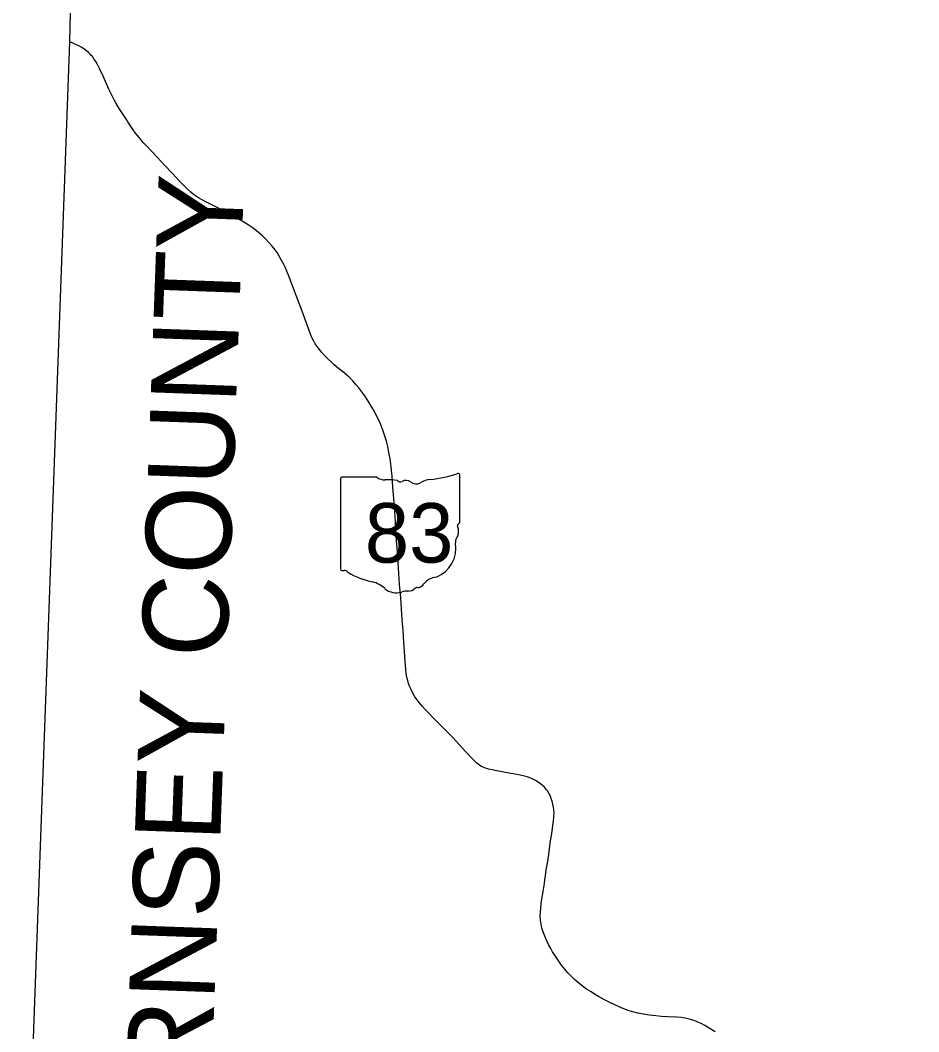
# Model space of a CAD drawing. Extents: x 2125567 to 2397567, y 653347 to 829347.
# Drawn here: x 2184839 to 2195345, y 708922 to 720753 of the extents above; entities that cross this region are included whole.
import ezdxf

# ---------------------------------------------------------------- set-up
doc = ezdxf.new("R2010")
doc.units = 0
for name, color, linetype in [('GM_X_County', 7, 'Continuous'), ('GM_X_County_Text', 7, 'Continuous'), ('GM_X_State_Route', 7, 'Continuous'), ('GM_X_State_Shield', 7, 'Continuous')]:
    doc.layers.add(name, color=color, linetype=linetype)

msp = doc.modelspace()

# ---------------------------------------------------------------- linework, layer by layer
at = {"layer": 'GM_X_County'}
msp.add_lwpolyline([(2195235, 695229), (2195244, 698121), (2195345, 704208), (2193259, 704276), (2191227, 704339), (2187691, 704452), (2186198, 704526), (2186181, 704528), (2186154, 704528), (2184839, 704570), (2185417, 720500), (2185450, 721840), (2185440, 722692), (2185445, 722809), (2185639, 727493), (2185641, 727535), (2185674, 729391), (2185791, 731433), (2186112, 740356), (2186166, 742913), (2186360, 747780)], dxfattribs=at)
at = {"layer": 'GM_X_State_Route'}
msp.add_lwpolyline([(2192963, 708921), (2192894, 708964), (2192843, 708994), (2192800, 709017), (2192761, 709035), (2192719, 709052), (2192676, 709066), (2192645, 709075), (2192613, 709081), (2192568, 709087), (2192512, 709092), (2192411, 709097), (2192338, 709101), (2192270, 709107), (2192191, 709116), (2192126, 709126), (2192059, 709140), (2192001, 709154), (2191947, 709170), (2191895, 709189), (2191840, 709212), (2191790, 709236), (2191734, 709263), (2191672, 709295), (2191600, 709334), (2191555, 709361), (2191513, 709387), (2191461, 709422), (2191445, 709433), (2191413, 709457), (2191369, 709491), (2191319, 709534), (2191279, 709573), (2191240, 709613), (2191206, 709653), (2191169, 709700), (2191135, 709748), (2191097, 709805), (2191064, 709858), (2191037, 709904), (2191016, 709944), (2190991, 709995), (2190972, 710040), (2190956, 710080), (2190943, 710120), (2190933, 710156), (2190928, 710181), (2190921, 710227), (2190919, 710273), (2190921, 710320), (2190925, 710366), (2190931, 710421), (2190943, 710496), (2190953, 710561), (2190967, 710655), (2190973, 710703), (2190980, 710746), (2190990, 710814), (2191003, 710894), (2191018, 710995), (2191028, 711066), (2191040, 711154), (2191053, 711235), (2191068, 711335), (2191075, 711390), (2191079, 711436), (2191080, 711481), (2191078, 711520), (2191075, 711546), (2191068, 711584), (2191058, 711619), (2191048, 711649), (2191033, 711685), (2191018, 711714), (2191003, 711739), (2190994, 711751), (2190986, 711763), (2190967, 711784), (2190945, 711804), (2190923, 711822), (2190893, 711843), (2190862, 711861), (2190831, 711877), (2190798, 711891), (2190767, 711902), (2190733, 711911), (2190669, 711926), (2190556, 711947), (2190411, 711972), (2190356, 711984), (2190314, 711994), (2190279, 712005), (2190261, 712013), (2190234, 712025), (2190212, 712038), (2190195, 712051), (2190177, 712065), (2190150, 712090), (2190106, 712134), (2190045, 712199), (2189896, 712363), (2189836, 712427), (2189762, 712501), (2189667, 712595), (2189619, 712644), (2189578, 712687), (2189538, 712731), (2189505, 712772), (2189478, 712806), (2189454, 712841), (2189431, 712881), (2189412, 712919), (2189396, 712956), (2189380, 712996), (2189370, 713030), (2189360, 713069), (2189353, 713111), (2189347, 713160), (2189340, 713258), (2189325, 713477), (2189315, 713614), (2189306, 713739), (2189287, 713996), (2189275, 714159), (2189250, 714531), (2189240, 714668), (2189232, 714773), (2189225, 714894), (2189211, 715113), (2189197, 715293), (2189187, 715426), (2189184, 715457), (2189176, 715531), (2189163, 715622), (2189150, 715696), (2189135, 715767), (2189120, 715830), (2189102, 715890), (2189084, 715946), (2189063, 716001), (2189042, 716052), (2189025, 716087), (2189001, 716137), (2188970, 716195), (2188943, 716240), (2188902, 716307), (2188867, 716358), (2188833, 716406), (2188797, 716453), (2188767, 716488), (2188726, 716534), (2188683, 716577), (2188659, 716600), (2188625, 716629), (2188561, 716680), (2188511, 716722), (2188481, 716748), (2188434, 716793), (2188399, 716828), (2188366, 716865), (2188336, 716900), (2188311, 716935), (2188289, 716968), (2188271, 716999), (2188254, 717035), (2188233, 717083), (2188202, 717166), (2188134, 717351), (2188085, 717483), (2188034, 717615), (2187983, 717750), (2187957, 717817), (2187936, 717865), (2187920, 717897), (2187891, 717952), (2187864, 718000), (2187841, 718036), (2187831, 718050), (2187818, 718068), (2187784, 718111), (2187750, 718151), (2187707, 718196), (2187672, 718230), (2187625, 718271), (2187582, 718306), (2187550, 718329), (2187504, 718360), (2187454, 718391), (2187356, 718449), (2187348, 718453), (2187313, 718473), (2187224, 718522), (2187166, 718552), (2187095, 718588), (2186987, 718642), (2186958, 718658), (2186924, 718677), (2186890, 718699), (2186866, 718716), (2186835, 718741), (2186798, 718774), (2186751, 718820), (2186695, 718879), (2186622, 718955), (2186528, 719055), (2186443, 719146), (2186311, 719288), (2186278, 719324), (2186233, 719376), (2186210, 719405), (2186188, 719433), (2186161, 719470), (2186128, 719519), (2186113, 719541), (2186097, 719565), (2186088, 719579), (2186041, 719650), (2185995, 719722), (2185965, 719773), (2185942, 719813), (2185897, 719900), (2185876, 719945), (2185807, 720097), (2185766, 720187), (2185743, 720234), (2185722, 720271), (2185701, 720303), (2185683, 720327), (2185669, 720342), (2185662, 720351), (2185636, 720376), (2185612, 720397), (2185583, 720418), (2185553, 720437), (2185524, 720453), (2185486, 720471), (2185456, 720483), (2185425, 720495), (2185418, 720497)], dxfattribs=at)
at = {"layer": 'GM_X_State_Shield'}
for p, q in [((2188585, 715391), (2188585, 714335)), ((2189007, 715409), (2188599, 715409)), ((2189977, 714883), (2189977, 715436)), ((2189977, 714883), (2189977, 714883))]:
    msp.add_line(p, q, dxfattribs=at)
for centre, radius, start, end in [((2189481, 716850), 1476, 275.8445, 288.9065), ((2189962, 715438), 15.5, 351.8621, 97.738), ((2188601, 715393), 16.1, 98.1301, 188.1301), ((2189104, 715532), 156, 231.6195, 271.1119), ((2189156, 714816), 562, 80.4867, 94.9883), ((2189283, 715399), 45.1, 219.7921, 297.1024), ((2189349, 715277), 93.8, 54.4667, 119.1411), ((2189470, 715444), 113, 233.8562, 294.8282), ((2189670, 715087), 297, 97.3462, 120.7689), ((2189974, 714842), 24, 107.944, 210.337), ((2189961, 714881), 16.6, 289.6038, 7.7341), ((2189821, 714772), 144, 340.033, 23.6496), ((2189564, 714581), 369, 292.3089, 8.9858), ((2190033, 714652), 105, 136.8065, 186.9296), ((2188601, 714332), 16.3, 171.9584, 258.3066), ((2188604, 714440), 124, 267.339, 280.6039), ((2188629, 714274), 44.8, 29.7484, 93.2717), ((2189194, 715223), 1066, 240.4129, 257.1985), ((2188877, 713860), 334, 47.1842, 75.836), ((2189464, 714232), 119, 282.8732, 323.2771), ((2189720, 714038), 202, 94.4031, 142.5768), ((2189237, 714268), 212, 230.7004, 286.2918), ((2189360, 713903), 174, 85.6951, 111.2099), ((2189375, 714189), 113, 268.777, 315.5493), ((2189477, 714087), 31.8, 65.7517, 132.6484)]:
    msp.add_arc(centre, radius, start, end, dxfattribs=at)

# ---------------------------------------------------------------- texts
at = {"layer": 'GM_X_County_Text'}
msp.add_text('GUERNSEY COUNTY', height=1000, rotation=87.9259, dxfattribs=at).set_placement((2186969, 705414))
at = {"layer": 'GM_X_State_Shield'}
msp.add_text('83', height=696.1, dxfattribs=at).set_placement((2188868, 714409))

doc.saveas('drawing.dxf')
